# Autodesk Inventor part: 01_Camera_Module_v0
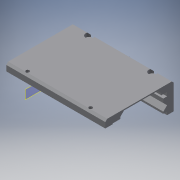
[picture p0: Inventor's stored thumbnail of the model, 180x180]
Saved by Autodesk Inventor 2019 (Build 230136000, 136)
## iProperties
Created: 2021-09
Part Number: 01_Camera_Module_v0
Material: Generisch
Document SubType Name: Modeling
Designer: Muriel
Density: 1 g/cm^3
Appearance: Vorgabe
Author: Muriel
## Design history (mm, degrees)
workplane "Arbeitsebene6"
sketch "Skizze6"
  geometry: L1 (7, 24)-(7, 1) reference; L2 (7, 1)-(8.5, 1) reference; L3 (8.5, 4)-(8.5, 1) reference; L4 (8.5, 4)-(11.3, 4) reference; L5 (11.3, 21)-(11.3, 4) reference; L6 (8.5, 21)-(11.3, 21) reference; L7 (8.5, 24)-(8.5, 21) reference; L8 (7, 24)-(8.5, 24) reference; L9 (8.5, -1)-(8.5, 1) reference; L10 (7, -1)-(8.5, -1) reference; L11 (7, -1)-(7, 1) reference; L12 (8.5, 24)-(8.5, 26) reference; L13 (7, 26)-(8.5, 26) reference; L14 (7, 24)-(7, 26) reference; L15 (12.2, -5.9)-(8.3, -5.9); L16 (3.5, 29.9)-(12.2, 29.9); L17 (12.2, 29.9)-(12.2, -5.9); L18 (7.8, 16.5)-(7.8, 25.5) reference; L19 (7.8, 25.5)-(-1.2, 25.5) reference; L20 (-1.2, 25.5)-(-1.2, 16.5) reference; L21 (-1.2, 16.5)-(7.8, 16.5) reference; L22 (3.5, 29.9)-(-1.8, 29.9); L23 (-1.8, 29.9)-(-1.8, 12); L24 (-1.8, 12)-(8.3, 12); L25 (4, 16.3)-(4, 25.7); L26 (5, 4.25)-(5, 20.75) reference; L27 (11.3, 21)-(11.3, 4) reference; L28 (8, 16.3)-(8, 25.7); L29 (8, 25.7)-(-1.4, 25.7); L30 (-1.4, 25.7)-(-1.4, 16.3); L31 (-1.4, 16.3)-(8, 16.3); L32 (4, 16.3)-(4, 25.7); L33 (7.8, 16.5)-(7.8, 25.5) reference; L34 (7.8, 25.5)-(-1.2, 25.5) reference; L35 (-1.2, 25.5)-(-1.2, 16.5) reference; L36 (-1.2, 16.5)-(7.8, 16.5) reference; L37 (-0.7, -1.5)-(8.3, -1.5) reference; L38 (8.5, 7.7)-(4.163, 7.7) reference; L39 (-0.9, 7.7)-(-0.9, -1.7) reference; L40 (8.3, -5.9)-(8.3, 4.497); L41 (8.3, -5.9)-(8.3, 12); L42 (4.166, 7.912)-(4.163, 7.7); C1 r 4 at (3.3, 21) reference; C2 r 4 at (3.3, 21) reference; 1 further point
  constraints: 36 end point, 4 horizontal, 4 parallel, 4 point on line, 2 perpendicular, 2 vertical, 8 other
  dimensions: "d41" = 14 distance between parallel lines of L23 L17; "d42" = 0.2 distance between parallel lines of L21 L31; "d48" = 4.2 distance between parallel lines of L29 L22 (derived); "d50" = 9 distance from line of L24 C1.centre; "d52" = 17.9 distance between parallel lines of L24 L22 (derived); "d53" = 3.9 distance between parallel lines of L17 L41; "d54" = 8.9 distance from line of L22 C2.centre; "d55" = 17.9 distance between parallel lines of L15 L24; "d58" = 8.9 distance from line of L17 C1.centre
  node "Referenz13"
  node "Referenz14"
  node "Referenz15"
  node "Referenz16"
  node "Referenz17"
  node "Referenz18"
  node "Referenz19"
  node "Referenz20"
  node "Referenz21"
  node "Referenz22"
  node "Referenz23"
workplane "Arbeitsebene7"
extrude "Extrusion6" new body sketch "Skizze6" stored distance "d43" = 2; taper "d44" = 0 deg
sketch "Skizze7"
  geometry: L1 (4.2, 0.4)-(13.6, 0.4) reference; L2 (4.2, 9.8)-(4.2, 0.4) reference; L3 (13.6, 9.8)-(4.2, 9.8) reference; L4 (13.6, 0.4)-(13.6, 9.8) reference; L5 (35.8, 10.1)-(17.9, 10.1) reference; L6 (35.8, 14)-(35.8, 10.1) reference; L7 (0, 14)-(35.8, 14) reference; L8 (0, 0)-(0, 14) reference; L9 (17.9, 0)-(0, 0) reference; L10 (17.9, 10.1)-(17.9, 0) reference; C1 r 4 at (8.9, 5.1) reference; 1 further point
extrude "Extrusion7" join sketch "Skizze7" distance "d56" = 2; taper "d57" = 0 deg
workplane "Arbeitsebene8"
sketch "Skizze8"
  geometry: L1 (1, 7)-(24, 7) reference; L2 (24, 7)-(24, 8.5) reference; L3 (16.25, 8.5)-(24, 8.5) reference; L4 (8.75, 8.5)-(16.25, 8.5) reference; L5 (1, 8.5)-(8.75, 8.5) reference; L6 (1, 7)-(1, 8.5) reference; L7 (26, 8.5)-(24, 8.5) reference; L8 (26, 7)-(26, 8.5) reference; L9 (26, 7)-(24, 7) reference; L10 (1, 8.5)-(-1, 8.5) reference; L11 (-1, 7)-(-1, 8.5) reference; L12 (1, 7)-(-1, 7) reference; L13 (-5.9, 12.2)-(-5.9, 8.3) reference; L14 (-5.9, 8.3)-(12, 8.3) reference; L15 (12, 8.3)-(12, -1.8) reference; L16 (12, -1.8)-(29.9, -1.8) reference; L17 (29.9, -1.8)-(29.9, 12.2) reference; L18 (29.9, 12.2)-(-5.9, 12.2) reference; L19 (25.7, 8)-(25.7, -1.4) reference; L20 (25.7, -1.4)-(16.3, -1.4) reference; L21 (16.3, -1.4)-(16.3, 8) reference; L22 (16.3, 8)-(25.7, 8) reference; L23 (29.9, 12.2)-(29.9, -1.8) reference; L24 (29.9, 12.2)-(-5.9, 12.2) reference; L25 (29.9, -1.8)-(26.4, -1.8); L26 (26.4, -1.8)-(26.4, 12.2); L27 (26.4, 12.2)-(29.9, 12.2); L28 (29.9, 12.2)-(29.9, -1.8); L29 (26.4, 12.2)-(23.4, 12.2); L30 (23.4, 12.2)-(23.4, 8.7); L31 (23.4, 8.7)-(26.4, 8.7); L32 (26.4, 8.7)-(26.4, 12.2); L33 (-5.9, 12.2)-(-5.9, 8.3) reference; L34 (-5.9, 8.3)-(12, 8.3) reference; L35 (-5.9, 12.2)-(-2, 12.2); L36 (-2, 12.2)-(-2, 8.3); L37 (-2, 8.3)-(-5.9, 8.3); L38 (-5.9, 8.3)-(-5.9, 12.2); L39 (26.4, -0.2)-(24.4, -0.2); L40 (24.4, -0.2)-(24.4, 0.8); L41 (24.4, 0.8)-(26.4, 0.8); L42 (26.4, 0.8)-(26.4, -0.2); L43 (23.4, 12.2)-(-2, 12.2); L44 (-2, 12.2)-(-2, 11.6); L45 (-2, 11.6)-(23.4, 11.6); L46 (23.4, 11.6)-(23.4, 12.2); L47 (2, 8.7)-(-2, 8.7); L48 (-2, 8.7)-(-2, 11.6); L49 (-2, 11.6)-(2, 11.6); L50 (2, 11.6)-(2, 8.7); L51 (21, 8.5)-(4, 8.5) reference; L52 (21, 8.5)-(21, 11.3) reference; L53 (4, 11.3)-(21, 11.3) reference; L54 (4, 8.5)-(4, 11.3) reference; L55 (1, 7)-(-1, 7) reference; L56 (26.4, 6.7)-(24.4, 6.7); L57 (24.4, 6.7)-(24.4, 4.7); L58 (24.4, 4.7)-(26.4, 4.7); L59 (26.4, 4.7)-(26.4, 6.7); L60 (29.9, 12.2)-(26.4, 12.2); L61 (26.4, 12.2)-(26.4, -1.8); L62 (26.4, -1.8)-(29.9, -1.8); L63 (29.9, -1.8)-(29.9, 12.2); 2 further points
  constraints: 64 end point, 16 parallel, 8 horizontal, 8 perpendicular, 5 point on line, 1 other
  dimensions: "d59" = 0.3 distance from line of L53.start L45; "d60" = 1 distance between parallel lines of L11 L48; "d61" = 0.2 distance from line of L47 L5.start; "d62" = 2 distance between parallel lines of L54 L50; "d63" = 0.2 distance between parallel lines of L7 L31; "d64" = 3 distance between parallel lines of L26 L30; "d65" = 0.4 distance between parallel lines of L26 L8; "d66" = 0.2 distance from line of point (23, -0.4) L39; "d67" = 1 distance between parallel lines of L39 L41; "d68" = 2 distance between parallel lines of L42 L40; "d69" = 2 distance of L58.end L57.end; "d70" = 2 distance of L57.end L56.end; "d71" = 0.3 distance between parallel lines of L9 L56
extrude "Extrusion8" join sketch "Skizze8" stored distance "d72" = 2; taper "d73" = 0 deg
sketch "Skizze9"
  geometry: L1 (51.8, 0)-(0, 0) reference; L2 (51.8, 0)-(51.8, 35.8) reference; L3 (0, 35.8)-(51.8, 35.8) reference; L4 (0, 0)-(0, 35.8) reference; L5 (5.1, 7.9)-(51.8, 7.9) reference; L6 (5.1, 3.5)-(51.8, 3.5) reference; L7 (5.1, 3.9)-(51.8, 3.9) reference; L8 (5.1, 32.3)-(51.8, 32.3) reference; L9 (50.05, 34.05)-(50.05, 1.75); L10 (50.05, 1.75)-(1.75, 1.75); L11 (1.75, 1.75)-(1.75, 34.05); L12 (1.75, 34.05)-(50.05, 34.05); 5 further points
  constraints: 10 end point, 4 point on line, 1 horizontal, 5 other
  dimensions: "d74" = 1.75 distance between parallel lines of L3 L12; "d75" = 11 distance of point (20.431, 34.05) point (9.431, 34.05); "d76" = 11 distance of point (31.431, 34.05) point (20.431, 34.05); "d77" = 11 distance of point (42.431, 34.05) point (31.431, 34.05)
hole "Bohrung1" sketch "Skizze9" at (9.431, 34.05), (42.431, 34.05) diameter "d78" = 1.8; stored, may be unused: countersink angle "d82" = 90 deg, drill point angle "d84" = 118 deg; dims "d79" = 6, "d80" = 4, "d81" = 2, "d83" = 12
sketch "Skizze10"
  geometry: C1 r 0.9 at (9.431, 1.75) reference; C2 r 0.9 at (42.431, 1.75) reference; 1 further point
  constraints: 2 centre point, 4 other
extrude "Extrusion9" cut sketch "Skizze10" extent not by distance; stored distance "d85" = 2; taper "d86" = 0 deg
chamfer "Fase1" distance "d87" = 1; stored, may be unused: second distance "d88" = 2, angle "d89" = 45 deg
chamfer "Fase2" distance "d90" = 1; stored, may be unused: second distance "d91" = 2, angle "d92" = 45 deg
sketch "Skizze11"
  geometry: L1 (49.8, 0.4)-(49.8, 9.8) reference; L2 (47.7, 0.4)-(47.7, 9.8) reference; C1 r 1.4 at (47.7, 5.1); 1 further point
  constraints: 1 centre point, 1 midpoint
  dimensions: "d93" = 2.8 diameter of C1
extrude "Extrusion10" cut sketch "Skizze11" distance "d94" = 10; taper "d95" = 0 deg
sketch "Skizze12"
  geometry: L1 (5.1, -12.4)-(5.1, -13.7) reference; L2 (5.1, -12.4)-(51.8, -12.4) reference; L3 (5.1, -14.4)-(51.8, -14.4) reference; L4 (51.8, -14.4)-(51.8, -12.4) reference; L5 (5.1, -12.4)-(51.8, -12.4) reference; L6 (5.1, -12.4)-(5.1, -13.7) reference; L7 (5.1, -14.4)-(5.1, -13.7) reference; L8 (5.1, -14.4)-(51.8, -14.4) reference; L9 (5.1, -14.4)-(9.499, -14.4); L10 (9.499, -14.4)-(9.499, -12.4); L11 (9.499, -12.4)-(5.1, -12.4); L12 (5.1, -12.4)-(5.1, -14.4); 1 further point
  constraints: 8 end point, 2 parallel, 1 horizontal, 1 perpendicular, 1 point on line
  node "Projizierte Kontur8"
workplane "Arbeitsebene9"
extrude "Extrusion11" cut sketch "Skizze12" stored distance "d96" = 2; taper "d97" = 0 deg
chamfer "Fase3" distance "d98" = 1.9; stored, may be unused: second distance "d99" = 2, angle "d100" = 45 deg
node "Volumenkörper2"
node "Projizierte Kontur5"
node "Referenz24"
node "Referenz25"
node "Referenz26"
node "Referenz27"
node "Referenz28"
node "Referenz29"
node "Referenz30"
node "Referenz31"
node "Projizierte Kontur6"
node "Referenz32"
node "Referenz33"
node "Projizierte Kontur7"
other parameters: "d39" = 1, "d51" = 17.4
